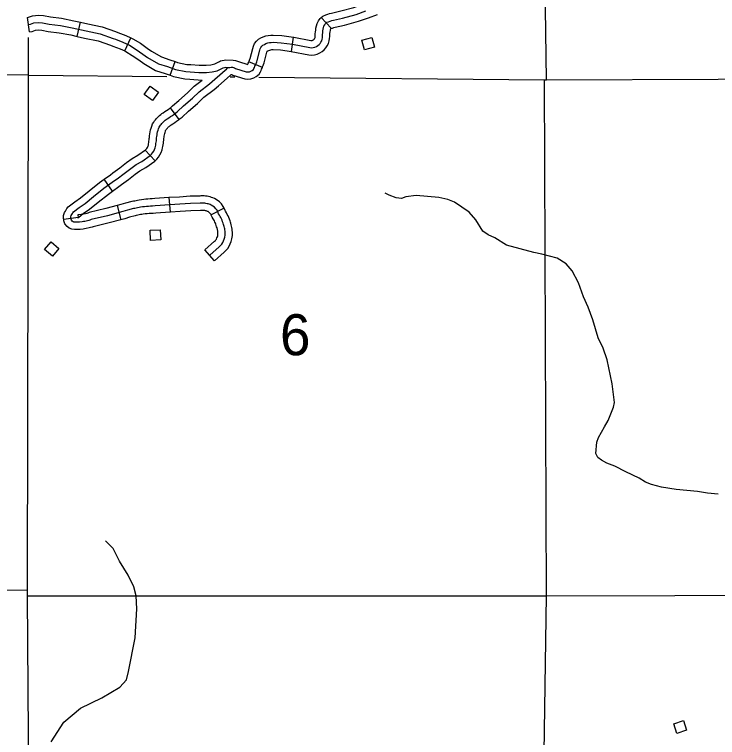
# Model space of a CAD drawing. Extents: x -19 to 366, y -4 to 359.
# Drawn here: x 139.362 to 140.733, y 202.778 to 204.187 of the extents above; entities that cross this region are included whole.
import ezdxf

# ---------------------------------------------------------------- set-up
doc = ezdxf.new("R2010")
doc.units = 0
for name, color, linetype in [('Level 2', 7, 'Continuous'), ('Level 32', 7, 'Continuous'), ('Level 35', 7, 'Continuous'), ('Level 4', 7, 'Continuous'), ('Level 5', 7, 'Continuous'), ('Level 56', 7, 'Continuous'), ('Level 60', 7, 'Continuous')]:
    doc.layers.add(name, color=color, linetype=linetype)

msp = doc.modelspace()

# ---------------------------------------------------------------- linework, layer by layer
at = {"layer": 'Level 2'}
for points in [[(139.3896, 204.0685), (139.3895, 204.1418)], [(139.3896, 204.0685), (138.383, 204.0778), (138.3761, 204.0776), (137.7294, 204.084)]]:
    msp.add_lwpolyline(points, dxfattribs=at)
at = {"layer": 'Level 32'}
for p, q in [((139.3916, 204.1531), (139.3873, 204.1812)), ((139.9799, 204.1602), (139.9603, 204.1808)), ((139.4847, 204.1439), (139.4908, 204.1717)), ((139.5772, 204.1157), (139.589, 204.1415)), ((139.9023, 204.1145), (139.9063, 204.1427)), ((139.6656, 204.0682), (139.6755, 204.0948)), ((139.8456, 204.0836), (139.8194, 204.0945)), ((139.6833, 203.9824), (139.6662, 204.005)), ((139.6366, 203.9016), (139.617, 203.9221)), ((139.5535, 203.8426), (139.537, 203.8657)), ((139.6634, 203.8299), (139.6655, 203.8016)), ((139.5624, 203.8142), (139.5697, 203.7868)), ((139.7709, 203.8095), (139.7459, 203.796)), ((139.4863, 203.7911), (139.4582, 203.787)), ((139.7522, 203.7069), (139.7334, 203.7281))]:
    msp.add_line(p, q, dxfattribs=at)
for points in [[(139.9603, 204.1808), (139.9635, 204.1838), (139.9696, 204.1861), (139.9731, 204.1873), (139.9766, 204.1884), (139.9804, 204.1896), (139.9987, 204.1937), (140.0242, 204.2006), (140.0427, 204.2073), (140.0606, 204.2136)], [(139.9642, 204.1579), (139.9647, 204.1611), (139.9657, 204.1641), (139.9671, 204.1669), (139.9689, 204.1694), (139.9712, 204.1715), (139.9743, 204.1727), (139.9776, 204.1738), (139.9808, 204.1748), (139.984, 204.1758), (140.0021, 204.1799), (140.0285, 204.187), (140.0475, 204.1939)], [(139.3873, 204.1812), (139.3896, 204.1815), (139.3971, 204.1842), (139.4089, 204.1852), (139.4189, 204.1846), (139.4322, 204.1819), (139.4539, 204.1793), (139.4777, 204.1746), (139.4908, 204.1717)], [(139.9063, 204.1427), (139.9066, 204.1426), (139.94, 204.1363), (139.9415, 204.1362), (139.9424, 204.1363), (139.9433, 204.1365), (139.9442, 204.1369), (139.9453, 204.1376), (139.9463, 204.1384), (139.947, 204.1392), (139.9475, 204.14), (139.9479, 204.1408), (139.9482, 204.1417), (139.9484, 204.143), (139.9485, 204.1457), (139.9488, 204.1493), (139.9492, 204.1529), (139.9496, 204.1565), (139.9501, 204.16), (139.9509, 204.1644), (139.9525, 204.1695), (139.9549, 204.1744), (139.9582, 204.1788), (139.9603, 204.1808)], [(139.9788, 204.1592), (139.9791, 204.1593), (139.9821, 204.1603), (139.985, 204.1613), (139.9877, 204.1621), (140.0055, 204.1661), (140.0328, 204.1735), (140.0523, 204.1805), (140.0701, 204.1868)], [(139.3894, 204.1671), (139.3931, 204.1677), (139.4001, 204.1702), (139.409, 204.1709), (139.4171, 204.1705), (139.43, 204.1679), (139.4516, 204.1653), (139.4747, 204.1607), (139.502, 204.1546), (139.5293, 204.1488), (139.5543, 204.1401), (139.5589, 204.1385), (139.5736, 204.1329), (139.5864, 204.1271), (139.5997, 204.1187), (139.6126, 204.1097), (139.6218, 204.1031), (139.643, 204.0908), (139.6606, 204.0852), (139.6762, 204.0794), (139.6963, 204.0754), (139.705, 204.075), (139.7218, 204.0737), (139.7368, 204.0737), (139.7475, 204.0749), (139.7571, 204.0768), (139.7628, 204.0795), (139.7691, 204.0827), (139.7746, 204.084), (139.778, 204.0832)], [(139.4908, 204.1717), (139.5051, 204.1685), (139.5332, 204.1625), (139.559, 204.1535), (139.5638, 204.1518), (139.579, 204.146), (139.589, 204.1415)], [(139.3916, 204.1531), (139.3966, 204.1539), (139.4031, 204.1562), (139.4092, 204.1567), (139.4153, 204.1563), (139.4277, 204.1538), (139.4494, 204.1513), (139.4718, 204.1468), (139.4847, 204.1439)], [(139.778, 204.0832), (139.7818, 204.0835), (139.7847, 204.0839), (139.787, 204.0839), (139.7893, 204.0834), (139.7914, 204.0827), (139.7934, 204.0816), (139.8142, 204.0753), (139.8172, 204.075), (139.8202, 204.0753), (139.8231, 204.0762), (139.8257, 204.0776), (139.828, 204.0796), (139.8291, 204.0816), (139.8301, 204.0837), (139.8311, 204.0858), (139.832, 204.0879), (139.8329, 204.0901), (139.8338, 204.0923), (139.8347, 204.0945), (139.8355, 204.0968), (139.8405, 204.1169), (139.8413, 204.1198), (139.8426, 204.1226), (139.8445, 204.125), (139.8467, 204.127), (139.8494, 204.1285), (139.8526, 204.13), (139.856, 204.1312), (139.8594, 204.132), (139.863, 204.1324), (139.8665, 204.1325), (139.882, 204.1317), (139.9043, 204.1286), (139.9381, 204.1222), (139.9414, 204.1219), (139.9447, 204.1222), (139.9479, 204.123), (139.951, 204.1244), (139.9538, 204.1262), (139.9561, 204.1281), (139.9581, 204.1303), (139.9598, 204.1328), (139.9612, 204.1356), (139.962, 204.1384), (139.9625, 204.1414), (139.9627, 204.1447), (139.963, 204.148), (139.9633, 204.1513), (139.9637, 204.1546), (139.9642, 204.1579)], [(139.902, 204.1146), (139.9361, 204.1081), (139.9413, 204.1077), (139.947, 204.1081), (139.9525, 204.1095), (139.9578, 204.1118), (139.9622, 204.1147), (139.9659, 204.1178), (139.9693, 204.1215), (139.9722, 204.1257), (139.9744, 204.1304), (139.9759, 204.1352), (139.9767, 204.1399), (139.9769, 204.1437), (139.9771, 204.1467), (139.9774, 204.1497), (139.9778, 204.1527), (139.9782, 204.1557), (139.9786, 204.1578), (139.9789, 204.1587), (139.9792, 204.1594), (139.9796, 204.1599), (139.9799, 204.1602)], [(139.4847, 204.1439), (139.499, 204.1407), (139.5255, 204.1351), (139.5496, 204.1267), (139.554, 204.1251), (139.5681, 204.1198), (139.5772, 204.1157)], [(139.589, 204.1415), (139.5931, 204.1396), (139.6076, 204.1306), (139.6209, 204.1213), (139.6295, 204.115), (139.6488, 204.1039), (139.6653, 204.0986), (139.6755, 204.0948)], [(139.8194, 204.0945), (139.8198, 204.0955), (139.8206, 204.0974), (139.8213, 204.0994), (139.8219, 204.1009), (139.8267, 204.1205), (139.828, 204.1249), (139.8305, 204.1301), (139.834, 204.1347), (139.8383, 204.1385), (139.8428, 204.1411), (139.8473, 204.1432), (139.8521, 204.1449), (139.8569, 204.146), (139.8619, 204.1466), (139.8667, 204.1467), (139.8833, 204.1459), (139.9063, 204.1427)], [(139.5772, 204.1157), (139.5796, 204.1145), (139.5919, 204.1069), (139.6044, 204.0981), (139.6141, 204.0911), (139.6372, 204.0778), (139.656, 204.0717), (139.6656, 204.0682)], [(139.8456, 204.0836), (139.8461, 204.0847), (139.8471, 204.0872), (139.848, 204.0896), (139.8491, 204.0926), (139.8542, 204.1133), (139.8546, 204.1148), (139.8548, 204.115), (139.8549, 204.1153), (139.8552, 204.1155), (139.856, 204.1159), (139.8579, 204.1168), (139.8599, 204.1175), (139.862, 204.118), (139.864, 204.1183), (139.8663, 204.1183), (139.8806, 204.1176), (139.9023, 204.1145)], [(139.6755, 204.0948), (139.6801, 204.0931), (139.6981, 204.0896), (139.7059, 204.0892), (139.7224, 204.0879), (139.7359, 204.0879), (139.7453, 204.0889), (139.7526, 204.0904), (139.7565, 204.0923), (139.7618, 204.0949)], [(139.7618, 204.0949), (139.7642, 204.0961), (139.7741, 204.0985)], [(139.7741, 204.0985), (139.7886, 204.098), (139.793, 204.0972), (139.7972, 204.0957), (139.7989, 204.0948), (139.8169, 204.0893), (139.817, 204.0893), (139.8173, 204.0898), (139.8181, 204.0916), (139.819, 204.0935), (139.8194, 204.0945)], [(139.7354, 203.8184), (139.7332, 203.8187), (139.731, 203.8189), (139.7288, 203.8189), (139.7265, 203.8189), (139.7243, 203.8187), (139.7051, 203.8183), (139.6846, 203.8168), (139.6652, 203.8158), (139.6367, 203.8136), (139.6315, 203.8132), (139.6275, 203.813), (139.6235, 203.8128), (139.6195, 203.8125), (139.6156, 203.8121), (139.6116, 203.8116), (139.6077, 203.8112), (139.605, 203.8105), (139.6023, 203.8099), (139.5997, 203.8093), (139.597, 203.8088), (139.5943, 203.8083), (139.5824, 203.8053), (139.5734, 203.8025), (139.5435, 203.7945), (139.5119, 203.7869), (139.5094, 203.7861), (139.5069, 203.7854), (139.5043, 203.7847), (139.4992, 203.7836), (139.4966, 203.7831), (139.494, 203.7826), (139.4888, 203.782), (139.4847, 203.7817), (139.4803, 203.7817), (139.4782, 203.782), (139.4763, 203.7829), (139.4745, 203.7841), (139.4731, 203.7857), (139.4724, 203.7879), (139.4721, 203.7902), (139.4721, 203.7925), (139.473, 203.795), (139.4739, 203.7968), (139.475, 203.7986), (139.476, 203.8002), (139.4772, 203.8019), (139.4881, 203.8103), (139.4998, 203.8183), (139.5164, 203.8323), (139.5367, 203.848), (139.5575, 203.8629), (139.5625, 203.8667), (139.5761, 203.8767), (139.5889, 203.8868), (139.5992, 203.8941), (139.6104, 203.9004), (139.6267, 203.9118), (139.6293, 203.9143), (139.6316, 203.9171), (139.6336, 203.9201), (139.6352, 203.9234), (139.6365, 203.9268), (139.6371, 203.9295), (139.6376, 203.9322), (139.6381, 203.935), (139.6385, 203.9377), (139.6389, 203.9406), (139.6392, 203.9434), (139.6394, 203.9462), (139.6396, 203.9491), (139.6401, 203.9521), (139.6406, 203.9551), (139.6413, 203.9582), (139.6422, 203.9611), (139.6431, 203.9641), (139.6442, 203.967), (139.6455, 203.9689), (139.6468, 203.9708), (139.6482, 203.9726), (139.6497, 203.9744), (139.6513, 203.9761), (139.6529, 203.9777), (139.6545, 203.9792), (139.6563, 203.9807), (139.6581, 203.9821), (139.6599, 203.9834), (139.6633, 203.9856), (139.6667, 203.9879), (139.67, 203.9902), (139.6733, 203.9926), (139.6765, 203.9951), (139.6798, 203.9976), (139.6918, 204.0086), (139.7091, 204.0238), (139.722, 204.0363), (139.7424, 204.0516), (139.7731, 204.0783), (139.7753, 204.0803), (139.778, 204.0832)], [(139.7599, 204.048), (139.7825, 204.0677), (139.7845, 204.0695), (139.7856, 204.0697), (139.7856, 204.0697), (139.7857, 204.0697), (139.7879, 204.0684), (139.8115, 204.0613), (139.8173, 204.0607), (139.8231, 204.0613), (139.8286, 204.063), (139.8337, 204.0658), (139.8393, 204.0705), (139.8418, 204.0752), (139.8429, 204.0775), (139.844, 204.0799), (139.8451, 204.0823), (139.8456, 204.0836)], [(139.6656, 204.0682), (139.6723, 204.0657), (139.6946, 204.0613), (139.7041, 204.0608), (139.7284, 204.0589)], [(139.6662, 204.005), (139.6679, 204.0063), (139.6706, 204.0085), (139.6824, 204.0192), (139.6995, 204.0342), (139.7127, 204.0471), (139.7284, 204.0589)], [(139.6833, 203.9824), (139.6852, 203.9838), (139.689, 203.9868), (139.7013, 203.998), (139.7188, 204.0133), (139.7312, 204.0255), (139.7513, 204.0405), (139.7599, 204.048)], [(139.617, 203.9221), (139.6189, 203.924), (139.6202, 203.9256), (139.6213, 203.9272), (139.6222, 203.9291), (139.6228, 203.9308), (139.6232, 203.9323), (139.6236, 203.9347), (139.6241, 203.9372), (139.6244, 203.9397), (139.6248, 203.9423), (139.6251, 203.9448), (139.6253, 203.9473), (139.6255, 203.9505), (139.626, 203.9544), (139.6267, 203.9581), (139.6276, 203.9617), (139.6286, 203.9652), (139.6297, 203.9688), (139.6315, 203.9734), (139.6337, 203.9769), (139.6353, 203.9792), (139.6372, 203.9816), (139.639, 203.9838), (139.641, 203.9859), (139.643, 203.9879), (139.6452, 203.9899), (139.6474, 203.9918), (139.6496, 203.9935), (139.652, 203.9952), (139.6555, 203.9975), (139.6586, 203.9996), (139.6617, 204.0018), (139.6648, 204.004), (139.6662, 204.005)], [(139.6366, 203.9016), (139.6397, 203.9046), (139.6431, 203.9086), (139.6459, 203.913), (139.6483, 203.9177), (139.6502, 203.9228), (139.651, 203.9267), (139.6516, 203.9297), (139.6521, 203.9327), (139.6526, 203.9358), (139.653, 203.9388), (139.6533, 203.942), (139.6536, 203.9451), (139.6538, 203.9476), (139.6541, 203.9499), (139.6545, 203.9522), (139.6551, 203.9546), (139.6558, 203.957), (139.6565, 203.9594), (139.6569, 203.9605), (139.6573, 203.961), (139.6582, 203.9624), (139.6593, 203.9637), (139.6604, 203.965), (139.6615, 203.9663), (139.6627, 203.9675), (139.6639, 203.9686), (139.6652, 203.9697), (139.6666, 203.9707), (139.6679, 203.9717), (139.6711, 203.9738), (139.6747, 203.9762), (139.6782, 203.9786), (139.6818, 203.9812), (139.6833, 203.9824)], [(139.537, 203.8657), (139.5491, 203.8744), (139.5541, 203.8781), (139.5674, 203.888), (139.5804, 203.8982), (139.5915, 203.9061), (139.6028, 203.9124), (139.6176, 203.9228), (139.617, 203.9221)], [(139.5535, 203.8426), (139.5658, 203.8514), (139.571, 203.8553), (139.5847, 203.8654), (139.5975, 203.8754), (139.6068, 203.8821), (139.618, 203.8884), (139.6357, 203.9008), (139.6366, 203.9016)], [(139.4582, 203.787), (139.4579, 203.7892), (139.4579, 203.795), (139.46, 203.8007), (139.4614, 203.8036), (139.4629, 203.806), (139.4644, 203.8084), (139.467, 203.8119), (139.4797, 203.8217), (139.4911, 203.8296), (139.5075, 203.8433), (139.5282, 203.8594), (139.537, 203.8657)], [(139.4865, 203.7901), (139.4871, 203.7911), (139.4875, 203.7919), (139.4964, 203.7988), (139.5084, 203.807), (139.5253, 203.8212), (139.5452, 203.8366), (139.5535, 203.8426)], [(139.6634, 203.8299), (139.6356, 203.8278), (139.6306, 203.8274), (139.6267, 203.8272), (139.6225, 203.8269), (139.6183, 203.8266), (139.6141, 203.8262), (139.6099, 203.8258), (139.6051, 203.8251), (139.6018, 203.8243), (139.5993, 203.8238), (139.5968, 203.8232), (139.5944, 203.8228), (139.5913, 203.8223), (139.5785, 203.819), (139.5695, 203.8161), (139.5624, 203.8142)], [(139.7709, 203.8095), (139.7691, 203.8127), (139.7657, 203.8174), (139.7617, 203.8215), (139.7573, 203.825), (139.7524, 203.8279), (139.7492, 203.8293), (139.7464, 203.8303), (139.7435, 203.8312), (139.7406, 203.8319), (139.7377, 203.8324), (139.7347, 203.8328), (139.7318, 203.8331), (139.7288, 203.8332), (139.7258, 203.8331), (139.7236, 203.8329), (139.7045, 203.8324), (139.6837, 203.831), (139.6643, 203.83), (139.6634, 203.8299)], [(139.5624, 203.8142), (139.54, 203.8083), (139.5081, 203.8006), (139.5053, 203.7998), (139.5031, 203.7991), (139.5008, 203.7985), (139.4964, 203.7975), (139.4941, 203.7971), (139.4919, 203.7967), (139.4875, 203.7961), (139.4856, 203.796), (139.4863, 203.7911)], [(139.7428, 203.7175), (139.7616, 203.7342), (139.7642, 203.7365), (139.7665, 203.7392), (139.7684, 203.7422), (139.7698, 203.7454), (139.7713, 203.7489), (139.7724, 203.7526), (139.7729, 203.7564), (139.7728, 203.7602), (139.7728, 203.7624), (139.7727, 203.7646), (139.7725, 203.7668), (139.7722, 203.769), (139.7718, 203.7711), (139.7712, 203.7733), (139.7706, 203.7754), (139.7698, 203.7775), (139.769, 203.7802), (139.768, 203.7829), (139.767, 203.7856), (139.7658, 203.7882), (139.7645, 203.7908), (139.7632, 203.7933), (139.7618, 203.7958), (139.7602, 203.7982), (139.7589, 203.8018), (139.7571, 203.8051), (139.7548, 203.8082), (139.7522, 203.8109), (139.7492, 203.8133), (139.746, 203.8152), (139.7439, 203.8161), (139.7419, 203.8168), (139.7397, 203.8175), (139.7376, 203.818), (139.7354, 203.8184)], [(139.6655, 203.8016), (139.6378, 203.7994), (139.6324, 203.799), (139.6282, 203.7988), (139.6245, 203.7986), (139.6208, 203.7983), (139.617, 203.7979), (139.6133, 203.7975), (139.6103, 203.7972), (139.6082, 203.7967), (139.6054, 203.796), (139.6026, 203.7954), (139.5995, 203.7948), (139.5972, 203.7944), (139.5863, 203.7917), (139.5774, 203.7888), (139.5697, 203.7868)], [(139.7459, 203.796), (139.745, 203.7975), (139.744, 203.799), (139.7426, 203.8004), (139.7412, 203.8015), (139.7396, 203.8025), (139.7387, 203.8028), (139.7374, 203.8033), (139.736, 203.8038), (139.7345, 203.8041), (139.7331, 203.8044), (139.7317, 203.8046), (139.7302, 203.8047), (139.7288, 203.8047), (139.7273, 203.8047), (139.7251, 203.8045), (139.7058, 203.8041), (139.6855, 203.8026), (139.6661, 203.8016), (139.6655, 203.8016)], [(139.7522, 203.7069), (139.7711, 203.7236), (139.7744, 203.7266), (139.778, 203.7308), (139.7809, 203.7354), (139.7828, 203.7396), (139.7848, 203.7441), (139.7863, 203.7498), (139.7871, 203.7557), (139.787, 203.7603), (139.787, 203.7626), (139.7869, 203.7656), (139.7866, 203.7684), (139.7862, 203.7713), (139.7856, 203.7742), (139.7849, 203.777), (139.7841, 203.7798), (139.7833, 203.782), (139.7825, 203.7847), (139.7813, 203.788), (139.7801, 203.7911), (139.7787, 203.7942), (139.7772, 203.7972), (139.7757, 203.8002), (139.7739, 203.8032), (139.773, 203.8046), (139.7718, 203.8077), (139.7709, 203.8095)], [(139.5697, 203.7868), (139.547, 203.7807), (139.5156, 203.7732), (139.5134, 203.7725), (139.5107, 203.7717), (139.5077, 203.7709), (139.502, 203.7696), (139.499, 203.7691), (139.4961, 203.7686), (139.4901, 203.7678), (139.4852, 203.7675), (139.4795, 203.7675), (139.4743, 203.7681), (139.469, 203.7706), (139.465, 203.7735), (139.4603, 203.7786), (139.4585, 203.7849), (139.4582, 203.787)], [(139.7334, 203.7281), (139.7521, 203.7448), (139.754, 203.7464), (139.755, 203.7476), (139.7558, 203.749), (139.7568, 203.7512), (139.7579, 203.7537), (139.7584, 203.7554), (139.7586, 203.7571), (139.7586, 203.7601), (139.7586, 203.7622), (139.7585, 203.7636), (139.7584, 203.7651), (139.7582, 203.7666), (139.7579, 203.7681), (139.7575, 203.7695), (139.7571, 203.771), (139.7564, 203.7729), (139.7555, 203.7757), (139.7547, 203.7779), (139.7539, 203.7801), (139.7529, 203.7823), (139.7519, 203.7844), (139.7508, 203.7865), (139.7496, 203.7885), (139.7475, 203.7918), (139.746, 203.7959), (139.7459, 203.796)]]:
    msp.add_lwpolyline(points, dxfattribs=at)
at = {"layer": 'Level 35'}
for points in [[(140.7346, 203.2516), (140.7138, 203.2539), (140.6938, 203.2573), (140.6522, 203.2607), (140.6238, 203.2653), (140.6046, 203.271), (140.5928, 203.2755), (140.5804, 203.2831), (140.5543, 203.2952), (140.5327, 203.3066), (140.5176, 203.3123), (140.5066, 203.3183), (140.4998, 203.3236), (140.4956, 203.3312), (140.4975, 203.3529), (140.5013, 203.362), (140.5126, 203.3832), (140.5202, 203.3953), (140.53, 203.4215), (140.5322, 203.4302), (140.528, 203.4667), (140.5178, 203.5137), (140.5102, 203.5361), (140.5007, 203.5566), (140.4901, 203.5914), (140.481, 203.6161), (140.4719, 203.6362), (140.4621, 203.6635), (140.45, 203.6874), (140.4379, 203.7007), (140.4205, 203.7121), (140.3906, 203.7196), (140.3751, 203.7227), (140.3214, 203.7374), (140.2991, 203.7515), (140.2858, 203.7572), (140.2753, 203.7644), (140.262, 203.7864), (140.2488, 203.8015), (140.22, 203.8212), (140.2072, 203.8262), (140.1894, 203.8303), (140.1455, 203.8341), (140.1251, 203.8314), (140.1168, 203.8284), (140.1066, 203.8292), (140.0926, 203.8345), (140.0847, 203.8386)], [(139.4334, 202.7691), (139.4582, 202.8076), (139.491, 202.8347), (139.5328, 202.8551), (139.5679, 202.8754), (139.5803, 202.8901), (139.5848, 202.906), (139.5972, 202.972), (139.6006, 203.0286), (139.5995, 203.0534), (139.595, 203.0715), (139.5837, 203.0941), (139.5667, 203.1213), (139.5543, 203.1462), (139.5396, 203.1609)]]:
    msp.add_lwpolyline(points, dxfattribs=at)
at = {"layer": 'Level 4'}
for points in [[(139.3955, 200.7198), (139.4, 201.0495), (139.3999, 201.0609), (139.3945, 202.0507), (139.3944, 202.0621), (139.3873, 203.0536), (139.3874, 203.0648), (139.3896, 204.0685)], [(139.3896, 204.0685), (139.659, 204.0661)], [(139.7826, 204.065), (139.792, 204.065)], [(139.8385, 204.0646), (140.3958, 204.0597), (140.3998, 204.0596), (141.4038, 204.0633), (141.4094, 204.0633), (141.4235, 204.0633)]]:
    msp.add_lwpolyline(points, dxfattribs=at)
at = {"layer": 'Level 5'}
for points in [[(140.3998, 204.0596), (140.3874, 204.9409)], [(140.3997, 203.0538), (140.3958, 204.0597)], [(138.3744, 203.0767), (139.3874, 203.0648)], [(139.3873, 203.0536), (140.3997, 203.0538)], [(140.385, 202.0476), (140.3997, 203.0538)], [(140.3997, 203.0538), (141.4008, 203.0562)]]:
    msp.add_lwpolyline(points, dxfattribs=at)
at = {"layer": 'Level 56'}
for points in [[(140.0639, 204.1228), (140.0448, 204.1177), (140.0397, 204.1368), (140.0588, 204.1419)], [(139.6312, 204.0194), (139.6153, 204.031), (139.6269, 204.047), (139.6428, 204.0354)], [(139.6266, 203.7662), (139.6462, 203.7673), (139.6473, 203.7476), (139.6276, 203.7465)], [(139.4488, 203.7309), (139.4362, 203.7158), (139.421, 203.7284), (139.4336, 203.7436)], [(140.6667, 202.8105), (140.6726, 202.7916), (140.6537, 202.7857), (140.6478, 202.8045)]]:
    msp.add_lwpolyline(points, close=True, dxfattribs=at)
at = {"layer": 'Level 60'}
for points in [[(146.7783, 1.697), (146.5788, 10.3131), (146.3785, 18.9294), (146.1776, 27.5458), (145.9759, 36.1624), (145.7736, 44.7791), (145.5705, 53.396), (145.3668, 62.013), (145.1624, 70.6301), (144.9572, 79.2474), (144.7514, 87.8648), (144.5449, 96.4823), (144.3377, 105.1), (144.1299, 113.7179), (143.9213, 122.3359), (143.712, 130.954), (143.5021, 139.5723), (143.2915, 148.1907), (143.0802, 156.8092), (142.8682, 165.4279), (142.6555, 174.0468), (142.4422, 182.6658), (142.2282, 191.2849), (142.0135, 199.9042), (141.7981, 208.5236), (141.582, 217.1432), (141.3653, 225.7629), (141.1479, 234.3828), (140.9298, 243.0028), (140.711, 251.623), (140.4916, 260.2433), (140.2715, 268.8638), (140.0508, 277.4844), (139.8293, 286.1051), (139.6072, 294.726), (139.3845, 303.3471), (139.161, 311.9683), (138.937, 320.5896), (138.7122, 329.2111), (138.4868, 337.8328), (138.2607, 346.4546)], [(139.4406, 1.5315), (139.2511, 10.1473), (139.0608, 18.7633), (138.8699, 27.3793), (138.6784, 35.9956), (138.4861, 44.6119), (138.2932, 53.2285), (138.0997, 61.8451), (137.9055, 70.4619), (137.7106, 79.0789), (137.5151, 87.6959), (137.319, 96.3132), (137.1221, 104.9306), (136.9247, 113.5481), (136.7265, 122.1658), (136.5278, 130.7836), (136.3283, 139.4016), (136.1282, 148.0197), (135.9275, 156.6379), (135.7261, 165.2564), (135.5241, 173.8749), (135.3214, 182.4936), (135.1181, 191.1125), (134.9141, 199.7315), (134.7095, 208.3506), (134.5043, 216.9699), (134.2984, 225.5894), (134.0919, 234.209), (133.8847, 242.8288), (133.6769, 251.4487), (133.4685, 260.0687), (133.2594, 268.6889), (133.0497, 277.3093), (132.8393, 285.9298), (132.6283, 294.5504), (132.4167, 303.1713), (132.2044, 311.7922), (131.9916, 320.4133), (131.778, 329.0346), (131.5639, 337.656), (131.3491, 346.2776)], [(0, 198.1326), (7.1014, 198.137), (14.2028, 198.1503), (21.3042, 198.1724), (28.4055, 198.2034), (35.5068, 198.2433), (42.6081, 198.292), (49.7092, 198.3496), (56.8103, 198.4161), (63.9113, 198.4913), (71.0123, 198.5755), (78.1131, 198.6685), (85.2137, 198.7704), (92.3143, 198.8811), (99.4147, 199.0007), (106.5149, 199.1291), (113.615, 199.2664), (120.7149, 199.4126), (127.8146, 199.5676), (134.9141, 199.7315), (142.0135, 199.9042), (149.1125, 200.0858), (156.2114, 200.2762), (163.31, 200.4755), (170.4084, 200.6837), (177.5065, 200.9007), (184.6043, 201.1265), (191.7018, 201.3612), (198.799, 201.6048), (205.896, 201.8572), (212.9926, 202.1185), (220.0888, 202.3886), (227.1848, 202.6676), (234.2803, 202.9554), (241.3755, 203.2521), (248.4704, 203.5576), (255.5648, 203.872), (262.6589, 204.1952), (269.7525, 204.5273), (276.8457, 204.8682), (283.9385, 205.218), (291.0309, 205.5766), (298.1228, 205.9441), (305.2142, 206.3204), (312.3051, 206.7056), (319.3956, 207.0996), (326.4856, 207.5024), (333.5751, 207.9141), (340.664, 208.3347)]]:
    msp.add_spline(points, degree=3, dxfattribs=at)

# ---------------------------------------------------------------- texts
at = {"layer": 'Level 5'}
msp.add_text('6', height=0.08, dxfattribs=at).set_placement((139.8799, 203.5226))

doc.saveas('drawing.dxf')
